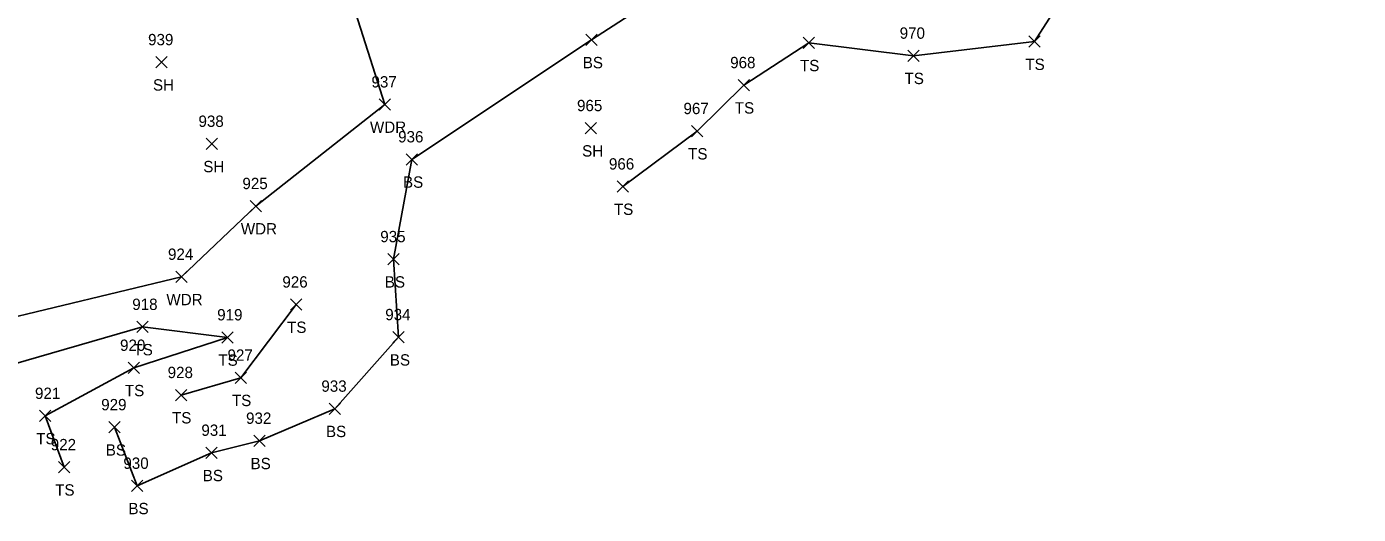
# Model space of a CAD drawing. Extents: x 1586965 to 1590952, y 716317 to 720029.
# Drawn here: x 1587407.7 to 1587642.6, y 719592.7 to 719678.7 of the extents above; entities that cross this region are included whole.
import ezdxf

# ---------------------------------------------------------------- set-up
doc = ezdxf.new("R2010")
doc.units = 0
for name, color, linetype in [('L_A', 7, 'Continuous'), ('L_I', 7, 'Continuous'), ('L_TIC', 7, 'Continuous'), ('LAWA', 7, 'Continuous'), ('LELB', 7, 'Continuous')]:
    doc.layers.add(name, color=color, linetype=linetype)

msp = doc.modelspace()

# ---------------------------------------------------------------- linework, layer by layer
at = {"layer": 'L_TIC'}
for points in [[(1587506.38, 719675.4), (1587508.38, 719677.4)], [(1587508.38, 719675.4), (1587506.38, 719677.4)], [(1587544.73, 719674.88), (1587546.73, 719676.88)], [(1587546.73, 719674.88), (1587544.73, 719676.88)], [(1587584.49, 719675.1), (1587586.49, 719677.1)], [(1587586.49, 719675.1), (1587584.49, 719677.1)], [(1587563.18, 719672.61), (1587565.18, 719674.61)], [(1587565.18, 719672.61), (1587563.18, 719674.61)], [(1587430.51, 719671.46), (1587432.51, 719673.46)], [(1587432.51, 719671.46), (1587430.51, 719673.46)], [(1587533.24, 719667.41), (1587535.24, 719669.41)], [(1587535.24, 719667.41), (1587533.24, 719669.41)], [(1587469.91, 719664.01), (1587471.91, 719666.01)], [(1587471.91, 719664.01), (1587469.91, 719666.01)], [(1587506.22, 719659.83), (1587508.22, 719661.83)], [(1587508.22, 719659.83), (1587506.22, 719661.83)], [(1587525, 719659.31), (1587527, 719661.31)], [(1587527, 719659.31), (1587525, 719661.31)], [(1587439.39, 719657.06), (1587441.39, 719659.06)], [(1587441.39, 719657.06), (1587439.39, 719659.06)], [(1587474.67, 719654.32), (1587476.67, 719656.32)], [(1587476.67, 719654.32), (1587474.67, 719656.32)], [(1587511.91, 719649.53), (1587513.91, 719651.53)], [(1587513.91, 719649.53), (1587511.91, 719651.53)], [(1587447.14, 719646.08), (1587449.14, 719648.08)], [(1587449.14, 719646.08), (1587447.14, 719648.08)], [(1587471.46, 719636.71), (1587473.46, 719638.71)], [(1587473.46, 719636.71), (1587471.46, 719638.71)], [(1587434.01, 719633.6), (1587436.01, 719635.6)], [(1587436.01, 719633.6), (1587434.01, 719635.6)], [(1587454.25, 719628.71), (1587456.25, 719630.71)], [(1587456.25, 719628.71), (1587454.25, 719630.71)], [(1587427.15, 719624.76), (1587429.15, 719626.76)], [(1587429.15, 719624.76), (1587427.15, 719626.76)], [(1587442.13, 719622.92), (1587444.13, 719624.92)], [(1587444.13, 719622.92), (1587442.13, 719624.92)], [(1587472.34, 719622.95), (1587474.34, 719624.95)], [(1587474.34, 719622.95), (1587472.34, 719624.95)], [(1587425.64, 719617.54), (1587427.64, 719619.54)], [(1587427.64, 719617.54), (1587425.64, 719619.54)], [(1587444.52, 719615.8), (1587446.52, 719617.8)], [(1587446.52, 719615.8), (1587444.52, 719617.8)], [(1587433.95, 719612.74), (1587435.95, 719614.74)], [(1587435.95, 719612.74), (1587433.95, 719614.74)], [(1587409.99, 719609.06), (1587411.99, 719611.06)], [(1587411.99, 719609.06), (1587409.99, 719611.06)], [(1587461.07, 719610.33), (1587463.07, 719612.33)], [(1587463.07, 719610.33), (1587461.07, 719612.33)], [(1587422.24, 719607.06), (1587424.24, 719609.06)], [(1587424.24, 719607.06), (1587422.24, 719609.06)], [(1587447.78, 719604.67), (1587449.78, 719606.67)], [(1587449.78, 719604.67), (1587447.78, 719606.67)], [(1587439.34, 719602.55), (1587441.34, 719604.55)], [(1587441.34, 719602.55), (1587439.34, 719604.55)], [(1587413.34, 719600.01), (1587415.34, 719602.01)], [(1587415.34, 719600.01), (1587413.34, 719602.01)], [(1587426.23, 719596.73), (1587428.23, 719598.73)], [(1587428.23, 719596.73), (1587426.23, 719598.73)]]:
    msp.add_lwpolyline(points, dxfattribs=at)
at = {"layer": 'LAWA'}
msp.add_lwpolyline([(1587401.27, 719626.51), (1587435.01, 719634.6), (1587448.14, 719647.08), (1587470.91, 719665.01), (1587461.04, 719696.06), (1587450.54, 719719.33), (1587487.07, 719738.78), (1587518.72, 719752.12), (1587550.39, 719765.58), (1587600.64, 719780.12), (1587625.51, 719792.71), (1587653.44, 719805), (1587664.38, 719814.47), (1587690.31, 719819.83), (1587699.11, 719820.97), (1587725.45, 719821.57), (1587738.15, 719822.66), (1587747.89, 719823.3), (1587771.26, 719823.5), (1587792.66, 719819.32), (1587813.67, 719812.11)], dxfattribs=at)
at = {"layer": 'LELB'}
for points in [[(1587423.24, 719608.06), (1587427.23, 719597.73), (1587440.34, 719603.55), (1587448.78, 719605.67), (1587462.07, 719611.33), (1587473.34, 719623.95), (1587472.46, 719637.71), (1587475.67, 719655.32), (1587507.38, 719676.4), (1587527.84, 719689.73), (1587549.35, 719714.4), (1587574.14, 719721.74), (1587593.15, 719738.05), (1587606.25, 719742.09)], [(1587423.24, 719608.06), (1587427.23, 719597.73), (1587440.34, 719603.55), (1587448.78, 719605.67), (1587462.07, 719611.33), (1587473.34, 719623.95), (1587472.46, 719637.71), (1587475.67, 719655.32), (1587507.38, 719676.4), (1587527.84, 719689.73), (1587549.35, 719714.4), (1587574.14, 719721.74), (1587593.15, 719738.05), (1587606.25, 719742.09)], [(1587512.91, 719650.53), (1587526, 719660.31), (1587534.24, 719668.41), (1587545.73, 719675.88), (1587564.18, 719673.61), (1587585.49, 719676.1), (1587592.78, 719687.55), (1587601.56, 719705.47), (1587618.49, 719703.82), (1587625.69, 719695.57)], [(1587512.91, 719650.53), (1587526, 719660.31), (1587534.24, 719668.41), (1587545.73, 719675.88), (1587564.18, 719673.61), (1587585.49, 719676.1), (1587592.78, 719687.55), (1587601.56, 719705.47), (1587618.49, 719703.82), (1587625.69, 719695.57)], [(1587455.25, 719629.71), (1587445.52, 719616.8), (1587434.95, 719613.74)], [(1587455.25, 719629.71), (1587445.52, 719616.8), (1587434.95, 719613.74)], [(1587355.75, 719603.68), (1587371.08, 719608.55), (1587403.18, 719618.57), (1587428.15, 719625.76), (1587443.13, 719623.92), (1587426.64, 719618.54), (1587410.99, 719610.06), (1587414.34, 719601.01)], [(1587355.75, 719603.68), (1587371.08, 719608.55), (1587403.18, 719618.57), (1587428.15, 719625.76), (1587443.13, 719623.92), (1587426.64, 719618.54), (1587410.99, 719610.06), (1587414.34, 719601.01)]]:
    msp.add_lwpolyline(points, dxfattribs=at)

# ---------------------------------------------------------------- texts
at = {"layer": 'L_A'}
for s, p in [('BS', (1587505.82, 719671.4)), ('TS', (1587544.14, 719670.88)), ('TS', (1587583.9, 719671.1)), ('SH', (1587430, 719667.46)), ('TS', (1587562.59, 719668.61)), ('TS', (1587532.65, 719663.41)), ('WDR', (1587468.28, 719660.01)), ('SH', (1587505.71, 719655.83)), ('TS', (1587524.41, 719655.31)), ('SH', (1587438.88, 719653.06)), ('BS', (1587474.11, 719650.32)), ('TS', (1587511.32, 719645.53)), ('WDR', (1587445.5, 719642.08)), ('BS', (1587470.9, 719632.71)), ('WDR', (1587432.37, 719629.6)), ('TS', (1587453.66, 719624.71)), ('TS', (1587426.56, 719620.76)), ('TS', (1587441.54, 719618.92)), ('BS', (1587471.79, 719618.95)), ('TS', (1587425.05, 719613.54)), ('TS', (1587443.93, 719611.8)), ('TS', (1587433.36, 719608.74)), ('BS', (1587460.52, 719606.33)), ('TS', (1587409.4, 719605.06)), ('BS', (1587421.68, 719603.06)), ('BS', (1587447.22, 719600.67)), ('BS', (1587438.78, 719598.55)), ('TS', (1587412.75, 719596.01)), ('BS', (1587425.67, 719592.73))]:
    msp.add_text(s, height=2, dxfattribs=at).set_placement(p)
at = {"layer": 'L_I'}
for s, p in [('939', (1587429.14, 719675.46)), ('970', (1587561.73, 719676.61)), ('968', (1587531.83, 719671.41)), ('937', (1587468.55, 719668.01)), ('965', (1587504.81, 719663.83)), ('967', (1587523.59, 719663.31)), ('938', (1587438.03, 719661.06)), ('936', (1587473.25, 719658.32)), ('966', (1587510.44, 719653.53)), ('925', (1587445.78, 719650.08)), ('935', (1587470.1, 719640.71)), ('924', (1587432.65, 719637.6)), ('926', (1587452.83, 719632.71)), ('918', (1587426.35, 719628.76)), ('919', (1587441.33, 719626.92)), ('934', (1587470.98, 719626.95)), ('920', (1587424.19, 719621.54)), ('927', (1587443.15, 719619.8)), ('928', (1587432.59, 719616.74)), ('933', (1587459.71, 719614.33)), ('921', (1587409.19, 719613.06)), ('929', (1587420.87, 719611.06)), ('932', (1587446.42, 719608.67)), ('931', (1587438.54, 719606.55)), ('922', (1587411.97, 719604.01)), ('930', (1587424.78, 719600.73))]:
    msp.add_text(s, height=2, dxfattribs=at).set_placement(p)

doc.saveas('drawing.dxf')
